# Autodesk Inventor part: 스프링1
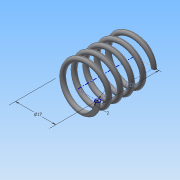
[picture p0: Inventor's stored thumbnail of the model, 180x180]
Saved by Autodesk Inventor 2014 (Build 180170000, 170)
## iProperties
Created: 2016-01
Part Number: 스프링1
Material: 강철, 탄소
Document SubType Name: Modeling
Designer: Administrator
Density: 7.87 g/cm^3
Appearance: 반연마
Mass: 6.46669 g
Surface Area: 16.7182 cm^2
Volume: 0.821689 cm^3
Author: Administrator
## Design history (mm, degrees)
sketch "스케치1"
  geometry: L1 (0, 0)-(8.5, 0); L2 (8.5, 0)-(8.5, 20.5); L3 (8.5, 20.5)-(0, 20.5); L4 (0, 20.5)-(0, 0); C1 r 1 at (8.5, 0)
  constraints: 8 end point, 2 parallel, 1 centre point, 1 coincident, 1 horizontal, 1 perpendicular
  dimensions: "d0" = 17 diameter of L2 L4; "d1" = 20.5 distance of L1.end L2.end (derived); "d2" = 2 diameter of C1
feature "코일1" sketch "스케치1" pitch "d3" = 10; turns "d5" = 5; dims "d4" = 20.5 (= d1), "d6" = 0, angle "d7" = 90 deg, angle "d8" = 90 deg, "d9" = 0, "d10" = 0
node "작업 평면1"
sketch "스케치2"
  geometry: L1 (-9.5, 0)-(-7.5, 0) reference; 1 further point
  constraints: 1 horizontal alignment
extrude "돌출1" cut sketch "스케치2" distance "d12" = 10; taper "d13" = 0 deg
node "작업 평면2"
sketch "스케치3"
  geometry: L1 (-7.5, 0)-(-9.5, 0) reference; 1 further point
  constraints: 1 horizontal alignment
extrude "돌출2" cut sketch "스케치3" distance "d15" = 10; taper "d16" = 0 deg
node "솔리드1"
node "절단 모서리 투영1"
node "절단 모서리 투영2"
other parameters: "d11" = 0, "d14" = 20.5 (= d1)
